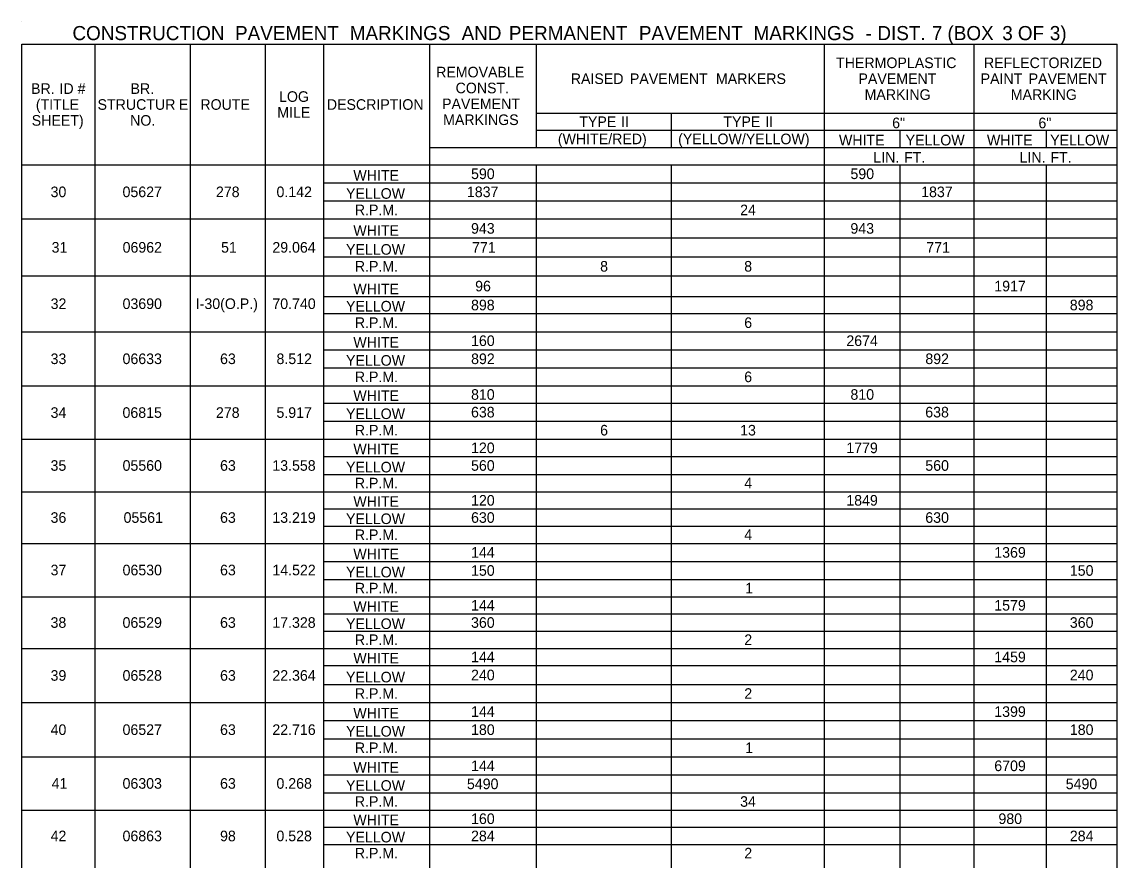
# Model space of a CAD drawing. Extents: x 544250 to 1930787, y -1948365 to 596640.
# Drawn here: x 551931 to 552552, y -1947835 to -1947360 of the extents above; entities that cross this region are included whole.
import ezdxf

# ---------------------------------------------------------------- set-up
doc = ezdxf.new("R2010")
doc.units = 0
doc.layers.add('Default', color=7, linetype='Continuous')

msp = doc.modelspace()

# ---------------------------------------------------------------- linework, layer by layer
at = {"layer": 'Default'}
for p, q in [((551930.97, -1947360), (551930.97, -1947360)), ((551930.97, -1947372.68), (552551.55, -1947372.68)), ((551930.97, -1948141.95), (551930.97, -1947372.68)), ((551972.4, -1948131.23), (551972.4, -1947372.68)), ((552026.52, -1948131.23), (552026.52, -1947372.68)), ((552068.93, -1948131.23), (552068.93, -1947372.68)), ((552102.08, -1948131.23), (552102.08, -1947372.68)), ((552162.04, -1948141.95), (552162.04, -1947372.68)), ((552222.49, -1947431.18), (552222.49, -1947372.68)), ((552385.8, -1948141.95), (552385.8, -1947372.68)), ((552470.63, -1947411.68), (552470.63, -1947372.68)), ((552470.63, -1948141.95), (552470.63, -1947372.68)), ((552551.55, -1948141.95), (552551.55, -1947372.68)), ((552222.49, -1947411.68), (552551.55, -1947411.68)), ((552299.03, -1947431.18), (552299.03, -1947411.68)), ((552222.49, -1947421.43), (552551.55, -1947421.43)), ((552428.7, -1947431.18), (552428.7, -1947421.43)), ((552470.63, -1947451.17), (552470.63, -1947421.43)), ((552511.58, -1947431.18), (552511.58, -1947421.43)), ((552162.04, -1947431.18), (552551.55, -1947431.18)), ((552162.04, -1947461.4), (552162.04, -1947431.18)), ((551930.97, -1947440.93), (552551.55, -1947440.93)), ((552026.52, -1948131.23), (552026.52, -1947440.93)), ((552068.93, -1948131.23), (552068.93, -1947440.93)), ((552102.08, -1947440.93), (552162.04, -1947440.93)), ((552102.08, -1947503.82), (552102.08, -1947440.93)), ((552222.49, -1948141.95), (552222.49, -1947440.93)), ((552299.03, -1948141.95), (552299.03, -1947440.93)), ((552385.8, -1947461.4), (552385.8, -1947440.93)), ((552428.7, -1948141.95), (552428.7, -1947440.93)), ((552511.58, -1948141.95), (552511.58, -1947440.93)), ((552102.08, -1947451.17), (552551.55, -1947451.17)), ((552511.58, -1947461.4), (552511.58, -1947451.17)), ((552102.08, -1947461.4), (552551.55, -1947461.4)), ((552162.04, -1947461.4), (552385.8, -1947461.4)), ((552385.8, -1947461.4), (552551.55, -1947461.4)), ((552470.63, -1947482.37), (552470.63, -1947461.4)), ((551930.97, -1947471.64), (552551.55, -1947471.64)), ((552102.08, -1947471.64), (552162.04, -1947471.64)), ((552162.04, -1947493.09), (552162.04, -1947471.64)), ((552385.8, -1947493.09), (552385.8, -1947471.64)), ((552102.08, -1947482.37), (552551.55, -1947482.37)), ((552511.58, -1947493.09), (552511.58, -1947482.37)), ((552102.08, -1947493.09), (552551.55, -1947493.09)), ((552470.63, -1947515.52), (552470.63, -1947493.09)), ((551930.97, -1947503.82), (552551.55, -1947503.82)), ((552102.08, -1947503.82), (552162.04, -1947503.82)), ((552162.04, -1947503.82), (552551.55, -1947503.82)), ((552162.04, -1947525.27), (552162.04, -1947503.82)), ((552385.8, -1947525.27), (552385.8, -1947503.82)), ((552102.08, -1947515.52), (552551.55, -1947515.52)), ((552511.58, -1947525.27), (552511.58, -1947515.52)), ((552102.08, -1947525.27), (552162.04, -1947525.27)), ((552102.08, -1947525.27), (552551.55, -1947525.27)), ((552470.63, -1947545.74), (552470.63, -1947525.27)), ((551930.97, -1947535.5), (552551.55, -1947535.5)), ((552102.08, -1947535.5), (552162.04, -1947535.5)), ((552102.08, -1947655.43), (552102.08, -1947535.5)), ((552162.04, -1947555.98), (552162.04, -1947535.5)), ((552385.8, -1947555.98), (552385.8, -1947535.5)), ((552102.08, -1947545.74), (552551.55, -1947545.74)), ((552511.58, -1947555.98), (552511.58, -1947545.74)), ((552102.08, -1947555.98), (552551.55, -1947555.98)), ((552470.63, -1947575.97), (552470.63, -1947555.98)), ((551930.97, -1947566.22), (552551.55, -1947566.22)), ((552102.08, -1947566.22), (552162.04, -1947566.22)), ((552162.04, -1947586.2), (552162.04, -1947566.22)), ((552385.8, -1947586.2), (552385.8, -1947566.22)), ((552102.08, -1947575.97), (552551.55, -1947575.97)), ((552511.58, -1947586.2), (552511.58, -1947575.97)), ((552102.08, -1947586.2), (552551.55, -1947586.2)), ((552470.63, -1947606.19), (552470.63, -1947586.2)), ((551930.97, -1947596.44), (552551.55, -1947596.44)), ((552102.08, -1947596.44), (552162.04, -1947596.44)), ((552162.04, -1947616.43), (552162.04, -1947596.44)), ((552385.8, -1947616.43), (552385.8, -1947596.44)), ((552102.08, -1947606.19), (552551.55, -1947606.19)), ((552511.58, -1947616.43), (552511.58, -1947606.19)), ((552102.08, -1947616.43), (552551.55, -1947616.43)), ((552470.63, -1947635.93), (552470.63, -1947616.43)), ((551930.97, -1947626.18), (552551.55, -1947626.18)), ((552102.08, -1947626.18), (552162.04, -1947626.18)), ((552162.04, -1947645.68), (552162.04, -1947626.18)), ((552385.8, -1947645.68), (552385.8, -1947626.18)), ((552102.08, -1947635.93), (552551.55, -1947635.93)), ((552511.58, -1947645.68), (552511.58, -1947635.93)), ((552102.08, -1947645.68), (552551.55, -1947645.68)), ((552470.63, -1947665.67), (552470.63, -1947645.68)), ((551930.97, -1947655.43), (552551.55, -1947655.43)), ((552162.04, -1947675.9), (552162.04, -1947655.43)), ((552385.8, -1947675.9), (552385.8, -1947655.43)), ((552102.08, -1947665.67), (552551.55, -1947665.67)), ((552511.58, -1947675.9), (552511.58, -1947665.67)), ((552102.08, -1947675.9), (552162.04, -1947675.9)), ((552102.08, -1947675.9), (552551.55, -1947675.9)), ((552470.63, -1947695.4), (552470.63, -1947675.9)), ((551930.97, -1947685.65), (552551.55, -1947685.65)), ((552162.04, -1947705.15), (552162.04, -1947685.65)), ((552385.8, -1947705.15), (552385.8, -1947685.65)), ((552102.08, -1947695.4), (552551.55, -1947695.4)), ((552511.58, -1947705.15), (552511.58, -1947695.4)), ((552102.08, -1947705.15), (552162.04, -1947705.15)), ((552102.08, -1947705.15), (552551.55, -1947705.15)), ((552470.63, -1947724.65), (552470.63, -1947705.15)), ((551930.97, -1947714.9), (552551.55, -1947714.9)), ((552162.04, -1947735.38), (552162.04, -1947714.9)), ((552385.8, -1947735.38), (552385.8, -1947714.9)), ((552102.08, -1947724.65), (552551.55, -1947724.65)), ((552511.58, -1947735.38), (552511.58, -1947724.65)), ((552102.08, -1947735.38), (552162.04, -1947735.38)), ((552102.08, -1947735.38), (552551.55, -1947735.38)), ((552470.63, -1947755.85), (552470.63, -1947735.38)), ((551930.97, -1947745.62), (552551.55, -1947745.62)), ((552162.04, -1947766.09), (552162.04, -1947745.62)), ((552385.8, -1947766.09), (552385.8, -1947745.62)), ((552102.08, -1947755.85), (552551.55, -1947755.85)), ((552511.58, -1947766.09), (552511.58, -1947755.85)), ((552102.08, -1947766.09), (552162.04, -1947766.09)), ((552102.08, -1947766.09), (552551.55, -1947766.09)), ((552470.63, -1947786.57), (552470.63, -1947766.09)), ((551930.97, -1947776.33), (552551.55, -1947776.33)), ((552162.04, -1947796.8), (552162.04, -1947776.33)), ((552385.8, -1947796.8), (552385.8, -1947776.33)), ((552102.08, -1947786.57), (552551.55, -1947786.57)), ((552511.58, -1947796.8), (552511.58, -1947786.57)), ((552102.08, -1947796.8), (552162.04, -1947796.8)), ((552102.08, -1947796.8), (552551.55, -1947796.8)), ((552470.63, -1947816.3), (552470.63, -1947796.8)), ((551930.97, -1947806.55), (552551.55, -1947806.55)), ((552162.04, -1947826.05), (552162.04, -1947806.55)), ((552385.8, -1947826.05), (552385.8, -1947806.55)), ((552102.08, -1947816.3), (552551.55, -1947816.3)), ((552511.58, -1947826.05), (552511.58, -1947816.3)), ((552102.08, -1947826.05), (552162.04, -1947826.05)), ((552102.08, -1947826.05), (552551.55, -1947826.05)), ((552470.63, -1947845.55), (552470.63, -1947826.05))]:
    msp.add_line(p, q, dxfattribs=at)

# ---------------------------------------------------------------- texts
for s, height, p in [('CONSTRUCTION', 8, (551959.61, -1947370.34)), (' PAVEMENT', 8, (552048.76, -1947370.34)), (' MARKINGS', 8, (552113.75, -1947370.34)), (' AND', 8, (552177.16, -1947370.34)), (' PERMANENT', 8, (552203.93, -1947370.34)), (' PAVEMENT', 8, (552277.61, -1947370.34)), (' MARKINGS', 8, (552342.59, -1947370.34)), (' DIST.', 8, (552412.75, -1947370.34)), (' 7', 8, (552443.65, -1947370.34)), (' (BOX', 8, (552452.48, -1947370.34)), (' 3', 8, (552483.51, -1947370.34)), (' OF', 8, (552492.35, -1947370.34)), (' 3)', 8, (552510.46, -1947370.34)), (' -', 8, (552406.01, -1947370.34)), ('THERMOPLASTIC', 6, (552392.33, -1947386.18)), ('REFLECTORIZED', 6, (552476.13, -1947386.18)), ('REMOVABLE', 6, (552165.69, -1947391.43)), ('RAISED', 6, (552241.99, -1947395.18)), (' PAVEMENT', 6, (552273.26, -1947395.18)), (' MARKERS', 6, (552322, -1947395.18)), ('PAVEMENT', 6, (552405.01, -1947395.18)), ('PAINT', 6, (552474.23, -1947395.18)), (' PAVEMENT', 6, (552499.21, -1947395.18)), ('BR.', 6, (551936.16, -1947400.8)), (' ID', 6, (551950.02, -1947400.8)), (' #', 6, (551960.32, -1947400.8)), ('BR.', 6, (551992.53, -1947400.8)), ('CONST.', 6, (552176.72, -1947400.43)), ('(TITLE', 6, (551938.86, -1947409.8)), ('LOG', 6, (552076.68, -1947405.3)), ('PAVEMENT', 6, (552169.06, -1947409.43)), ('MARKING', 6, (552408.45, -1947404.18)), ('MARKING', 6, (552491.32, -1947404.18)), ('STRUCTUR', 6, (551973.84, -1947409.8)), ('E', 6, (552019.91, -1947409.8)), ('ROUTE', 6, (552032.09, -1947409.8)), ('MILE', 6, (552075.7, -1947414.3)), ('DESCRIPTION', 6, (552103.75, -1947409.8)), ('SHEET)', 6, (551936.53, -1947418.8)), ('NO.', 6, (551992.3, -1947418.8)), ('MARKINGS', 6, (552169.65, -1947418.43)), ('TYPE', 6, (552246.8, -1947419.55)), (' II', 6, (552268.28, -1947419.55)), ('TYPE', 6, (552328.46, -1947419.55)), (' II', 6, (552349.94, -1947419.55)), ('6"', 6, (552424.11, -1947420.23)), ('6"', 6, (552506.98, -1947420.23)), ('(WHITE/RED)', 6, (552234.67, -1947429.3)), ('(YELLOW/YELLOW)', 6, (552302.82, -1947429.3)), ('WHITE', 6, (552393.96, -1947429.98)), ('YELLOW', 6, (552431.74, -1947429.98)), ('WHITE', 6, (552477.81, -1947429.98)), ('YELLOW', 6, (552513.64, -1947429.98)), ('LIN.', 6, (552413.43, -1947439.73)), (' FT.', 6, (552428.68, -1947439.73)), ('LIN.', 6, (552496.3, -1947439.73)), (' FT.', 6, (552511.56, -1947439.73)), ('WHITE', 6, (552118.78, -1947449.97)), ('590', 6, (552185.48, -1947449.05)), ('590', 6, (552400.47, -1947449.05)), ('30', 6, (551947.23, -1947459.29)), ('05627', 6, (551988, -1947459.29)), ('278', 6, (552040.92, -1947459.29)), ('0.142', 6, (552075.24, -1947459.29)), ('1837', 6, (552183.14, -1947459.29)), ('1837', 6, (552440.54, -1947459.29)), ('YELLOW', 6, (552114.64, -1947460.2)), ('R.P.M.', 6, (552119.62, -1947469.52)), ('24', 6, (552337.96, -1947469.52)), ('WHITE', 6, (552118.78, -1947481.17)), ('943', 6, (552185.47, -1947480)), ('943', 6, (552400.45, -1947480)), ('31', 6, (551947.8, -1947490.73)), ('06962', 6, (551988.03, -1947490.73)), ('51', 6, (552043.83, -1947490.73)), ('29.064', 6, (552072.89, -1947490.73)), ('YELLOW', 6, (552114.64, -1947491.89)), ('771', 6, (552186.05, -1947490.73)), ('771', 6, (552443.45, -1947490.73)), ('R.P.M.', 6, (552119.62, -1947501.45)), ('8', 6, (552258.62, -1947501.45)), ('8', 6, (552340.27, -1947501.45)), ('WHITE', 6, (552118.78, -1947514.32)), ('96', 6, (552187.8, -1947512.67)), ('1917', 6, (552481.97, -1947512.67)), ('32', 6, (551947.25, -1947522.66)), ('03690', 6, (551988.01, -1947522.66)), ('I-30(O.P.)', 6, (552029.48, -1947522.66)), ('70.740', 6, (552072.89, -1947522.66)), ('YELLOW', 6, (552114.64, -1947524.07)), ('898', 6, (552185.46, -1947523.39)), ('898', 6, (552524.76, -1947523.39)), ('R.P.M.', 6, (552119.62, -1947533.39)), ('6', 6, (552340.28, -1947533.39)), ('WHITE', 6, (552118.78, -1947544.54)), ('160', 6, (552185.48, -1947543.62)), ('2674', 6, (552398.14, -1947543.62)), ('33', 6, (551947.22, -1947553.86)), ('06633', 6, (551988, -1947553.86)), ('63', 6, (552043.25, -1947553.86)), ('8.512', 6, (552075.24, -1947553.86)), ('YELLOW', 6, (552114.64, -1947554.78)), ('892', 6, (552185.5, -1947553.86)), ('892', 6, (552442.9, -1947553.86)), ('R.P.M.', 6, (552119.62, -1947564.1)), ('6', 6, (552340.28, -1947564.1)), ('WHITE', 6, (552118.78, -1947574.77)), ('810', 6, (552185.48, -1947574.09)), ('810', 6, (552400.47, -1947574.09)), ('34', 6, (551947.23, -1947584.33)), ('06815', 6, (551987.98, -1947584.33)), ('278', 6, (552040.92, -1947584.33)), ('5.917', 6, (552075.21, -1947584.33)), ('YELLOW', 6, (552114.64, -1947585)), ('638', 6, (552185.46, -1947584.09)), ('638', 6, (552442.86, -1947584.09)), ('R.P.M.', 6, (552119.62, -1947594.32)), ('6', 6, (552258.62, -1947594.32)), ('13', 6, (552337.95, -1947594.32)), ('WHITE', 6, (552118.78, -1947604.99)), ('120', 6, (552185.48, -1947604.32)), ('1779', 6, (552398.12, -1947604.32)), ('35', 6, (551947.19, -1947614.31)), ('05560', 6, (551988.01, -1947614.31)), ('63', 6, (552043.25, -1947614.31)), ('13.558', 6, (552072.88, -1947614.31)), ('560', 6, (552185.48, -1947614.31)), ('560', 6, (552442.88, -1947614.31)), ('YELLOW', 6, (552114.64, -1947615.23)), ('R.P.M.', 6, (552119.62, -1947624.3)), ('4', 6, (552340.29, -1947624.3)), ('WHITE', 6, (552118.78, -1947634.73)), ('120', 6, (552185.48, -1947634.05)), ('1849', 6, (552398.12, -1947634.05)), ('36', 6, (551947.22, -1947643.8)), ('05561', 6, (551988.58, -1947643.8)), ('63', 6, (552043.25, -1947643.8)), ('13.219', 6, (552072.88, -1947643.8)), ('YELLOW', 6, (552114.64, -1947644.48)), ('630', 6, (552185.48, -1947643.8)), ('630', 6, (552442.88, -1947643.8)), ('R.P.M.', 6, (552119.62, -1947653.55)), ('4', 6, (552340.29, -1947653.55)), ('144', 6, (552185.48, -1947663.55)), ('1369', 6, (552481.97, -1947663.55)), ('WHITE', 6, (552118.78, -1947664.47)), ('37', 6, (551947.22, -1947673.54)), ('06530', 6, (551988.01, -1947673.54)), ('63', 6, (552043.25, -1947673.54)), ('14.522', 6, (552072.91, -1947673.54)), ('YELLOW', 6, (552114.64, -1947674.7)), ('150', 6, (552185.48, -1947673.79)), ('150', 6, (552524.78, -1947673.79)), ('R.P.M.', 6, (552119.62, -1947683.78)), ('1', 6, (552340.86, -1947683.78)), ('WHITE', 6, (552118.78, -1947694.2)), ('144', 6, (552185.48, -1947693.53)), ('1579', 6, (552481.97, -1947693.53)), ('38', 6, (551947.21, -1947703.28)), ('06529', 6, (551988, -1947703.28)), ('63', 6, (552043.25, -1947703.28)), ('17.328', 6, (552072.88, -1947703.28)), ('YELLOW', 6, (552114.64, -1947703.95)), ('360', 6, (552185.48, -1947703.28)), ('360', 6, (552524.78, -1947703.28)), ('R.P.M.', 6, (552119.62, -1947713.03)), ('2', 6, (552340.31, -1947713.03)), ('WHITE', 6, (552118.78, -1947723.45)), ('144', 6, (552185.48, -1947722.78)), ('1459', 6, (552481.97, -1947722.78)), ('39', 6, (551947.21, -1947733.26)), ('06528', 6, (551988, -1947733.26)), ('63', 6, (552043.25, -1947733.26)), ('22.364', 6, (552072.89, -1947733.26)), ('YELLOW', 6, (552114.64, -1947734.18)), ('240', 6, (552185.48, -1947733.02)), ('240', 6, (552524.78, -1947733.02)), ('R.P.M.', 6, (552119.62, -1947743.5)), ('2', 6, (552340.31, -1947743.5)), ('WHITE', 6, (552118.78, -1947754.65)), ('144', 6, (552185.48, -1947753.74)), ('1399', 6, (552481.97, -1947753.74)), ('40', 6, (551947.23, -1947763.97)), ('06527', 6, (551988, -1947763.97)), ('63', 6, (552043.25, -1947763.97)), ('22.716', 6, (552072.88, -1947763.97)), ('YELLOW', 6, (552114.64, -1947764.89)), ('180', 6, (552185.48, -1947763.97)), ('180', 6, (552524.78, -1947763.97)), ('R.P.M.', 6, (552119.62, -1947774.21)), ('1', 6, (552340.86, -1947774.21)), ('WHITE', 6, (552118.78, -1947785.37)), ('144', 6, (552185.48, -1947784.45)), ('6709', 6, (552481.97, -1947784.45)), ('41', 6, (551947.8, -1947794.44)), ('06303', 6, (551988, -1947794.44)), ('63', 6, (552043.25, -1947794.44)), ('0.268', 6, (552075.21, -1947794.44)), ('YELLOW', 6, (552114.64, -1947795.6)), ('5490', 6, (552183.15, -1947794.69)), ('5490', 6, (552522.45, -1947794.69)), ('R.P.M.', 6, (552119.62, -1947804.68)), ('34', 6, (552337.96, -1947804.68)), ('WHITE', 6, (552118.78, -1947815.1)), ('160', 6, (552185.48, -1947814.43)), ('980', 6, (552484.32, -1947814.43)), ('42', 6, (551947.25, -1947824.18)), ('06863', 6, (551988, -1947824.18)), ('98', 6, (552043.25, -1947824.18)), ('0.528', 6, (552075.21, -1947824.18)), ('YELLOW', 6, (552114.64, -1947824.85)), ('284', 6, (552185.48, -1947824.18)), ('284', 6, (552524.78, -1947824.18)), ('R.P.M.', 6, (552119.62, -1947833.93)), ('2', 6, (552340.31, -1947833.93))]:
    msp.add_text(s, height=height, dxfattribs=at).set_placement(p)

doc.saveas('drawing.dxf')
